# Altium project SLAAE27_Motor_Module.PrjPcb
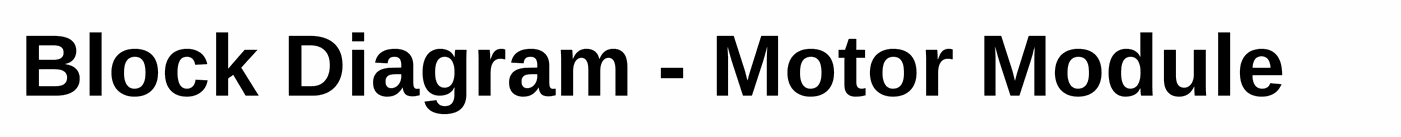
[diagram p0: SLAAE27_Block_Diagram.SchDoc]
Assembly Variant: 001; CopyrightYear: 2021; EVM_Orderable: N/A; PCB_Layout: Tessolve; PCB_Rev: E1; PRJ_Customer: Public Release; PRJ_Engineer: Sakshi Markhedkar; PRJ_Number: SLAAE27; PRJ_Title: SLAAE27_Motor_Module; SCH_Rev: E1; TechSupport: http://www.ti.com/support; TID: N/A
3 sheets, 169 parts. Net scope: global (net labels, ports and power ports of the same name join across sheets).
Board file: SLAAE27_Motor_Module_PCB.PcbDoc
Sheets:
  SLAAE27_Block_Diagram.SchDoc
  SLAAE27_MCU_&_Motor_Drivers.SchDoc
  SLAAE27_Motor_Module_Hardware.SchDoc

## Sheet SLAAE27_Block_Diagram.SchDoc: SLAAE27_Block_Diagram
size A2; Date: Not shown in title block; ApprovedBy: Not shown in title block; CheckedBy: Not shown in title block; Author: Not shown in title block; CompanyName: Not shown in title block; DrawnBy: Sakshi Markhedkar; Engineer: Not shown in title block; Organization: Not shown in title block; Address1: Not shown in title block; Address2: Not shown in title block; Address3: Not shown in title block; Address4: Not shown in title block; DocumentNumber: 1; Revision: Use project parameter SCH_Rev; SheetNumber: 1; SheetTotal: 3; PageSetup: Record=PageOptions¦CenterHorizontal=True¦CenterVertical=True¦PrintScale=1.00¦XCorrection=1.00¦YCorrection=1.00¦PrintKind=0¦BorderSize=5000000¦LeftOffset=0¦BottomOffset=0¦Orientation=2¦PaperLength=1000¦PaperWidth=1000¦Scale=100¦PaperSource=15¦PrintQuality=600¦MediaType=1¦DitherType=10¦PaperKind=Letter¦PrintScaleMode=1

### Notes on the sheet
- Block Diagram - Motor Module

## Sheet SLAAE27_MCU_&_Motor_Drivers.SchDoc: SLAAE27_MCU_&_Motor_Drivers
size A2; Date: Not shown in title block; ApprovedBy: Not shown in title block; CheckedBy: Not shown in title block; Author: Not shown in title block; CompanyName: Not shown in title block; DrawnBy: Sakshi Markhedkar; Engineer: Not shown in title block; Organization: Not shown in title block; Address1: Not shown in title block; Address2: Not shown in title block; Address3: Not shown in title block; Address4: Not shown in title block; DocumentNumber: 2; Revision: Use project parameter SCH_Rev; SheetNumber: 2; SheetTotal: 3; PageSetup: Record=PageOptions¦CenterHorizontal=True¦CenterVertical=True¦PrintScale=1.00¦XCorrection=1.00¦YCorrection=1.00¦PrintKind=0¦BorderSize=5000000¦LeftOffset=0¦BottomOffset=0¦Orientation=2¦PaperLength=1000¦PaperWidth=1000¦Scale=100¦PaperSource=15¦PrintQuality=600¦MediaType=1¦DitherType=10¦PaperKind=Letter¦PrintScaleMode=1
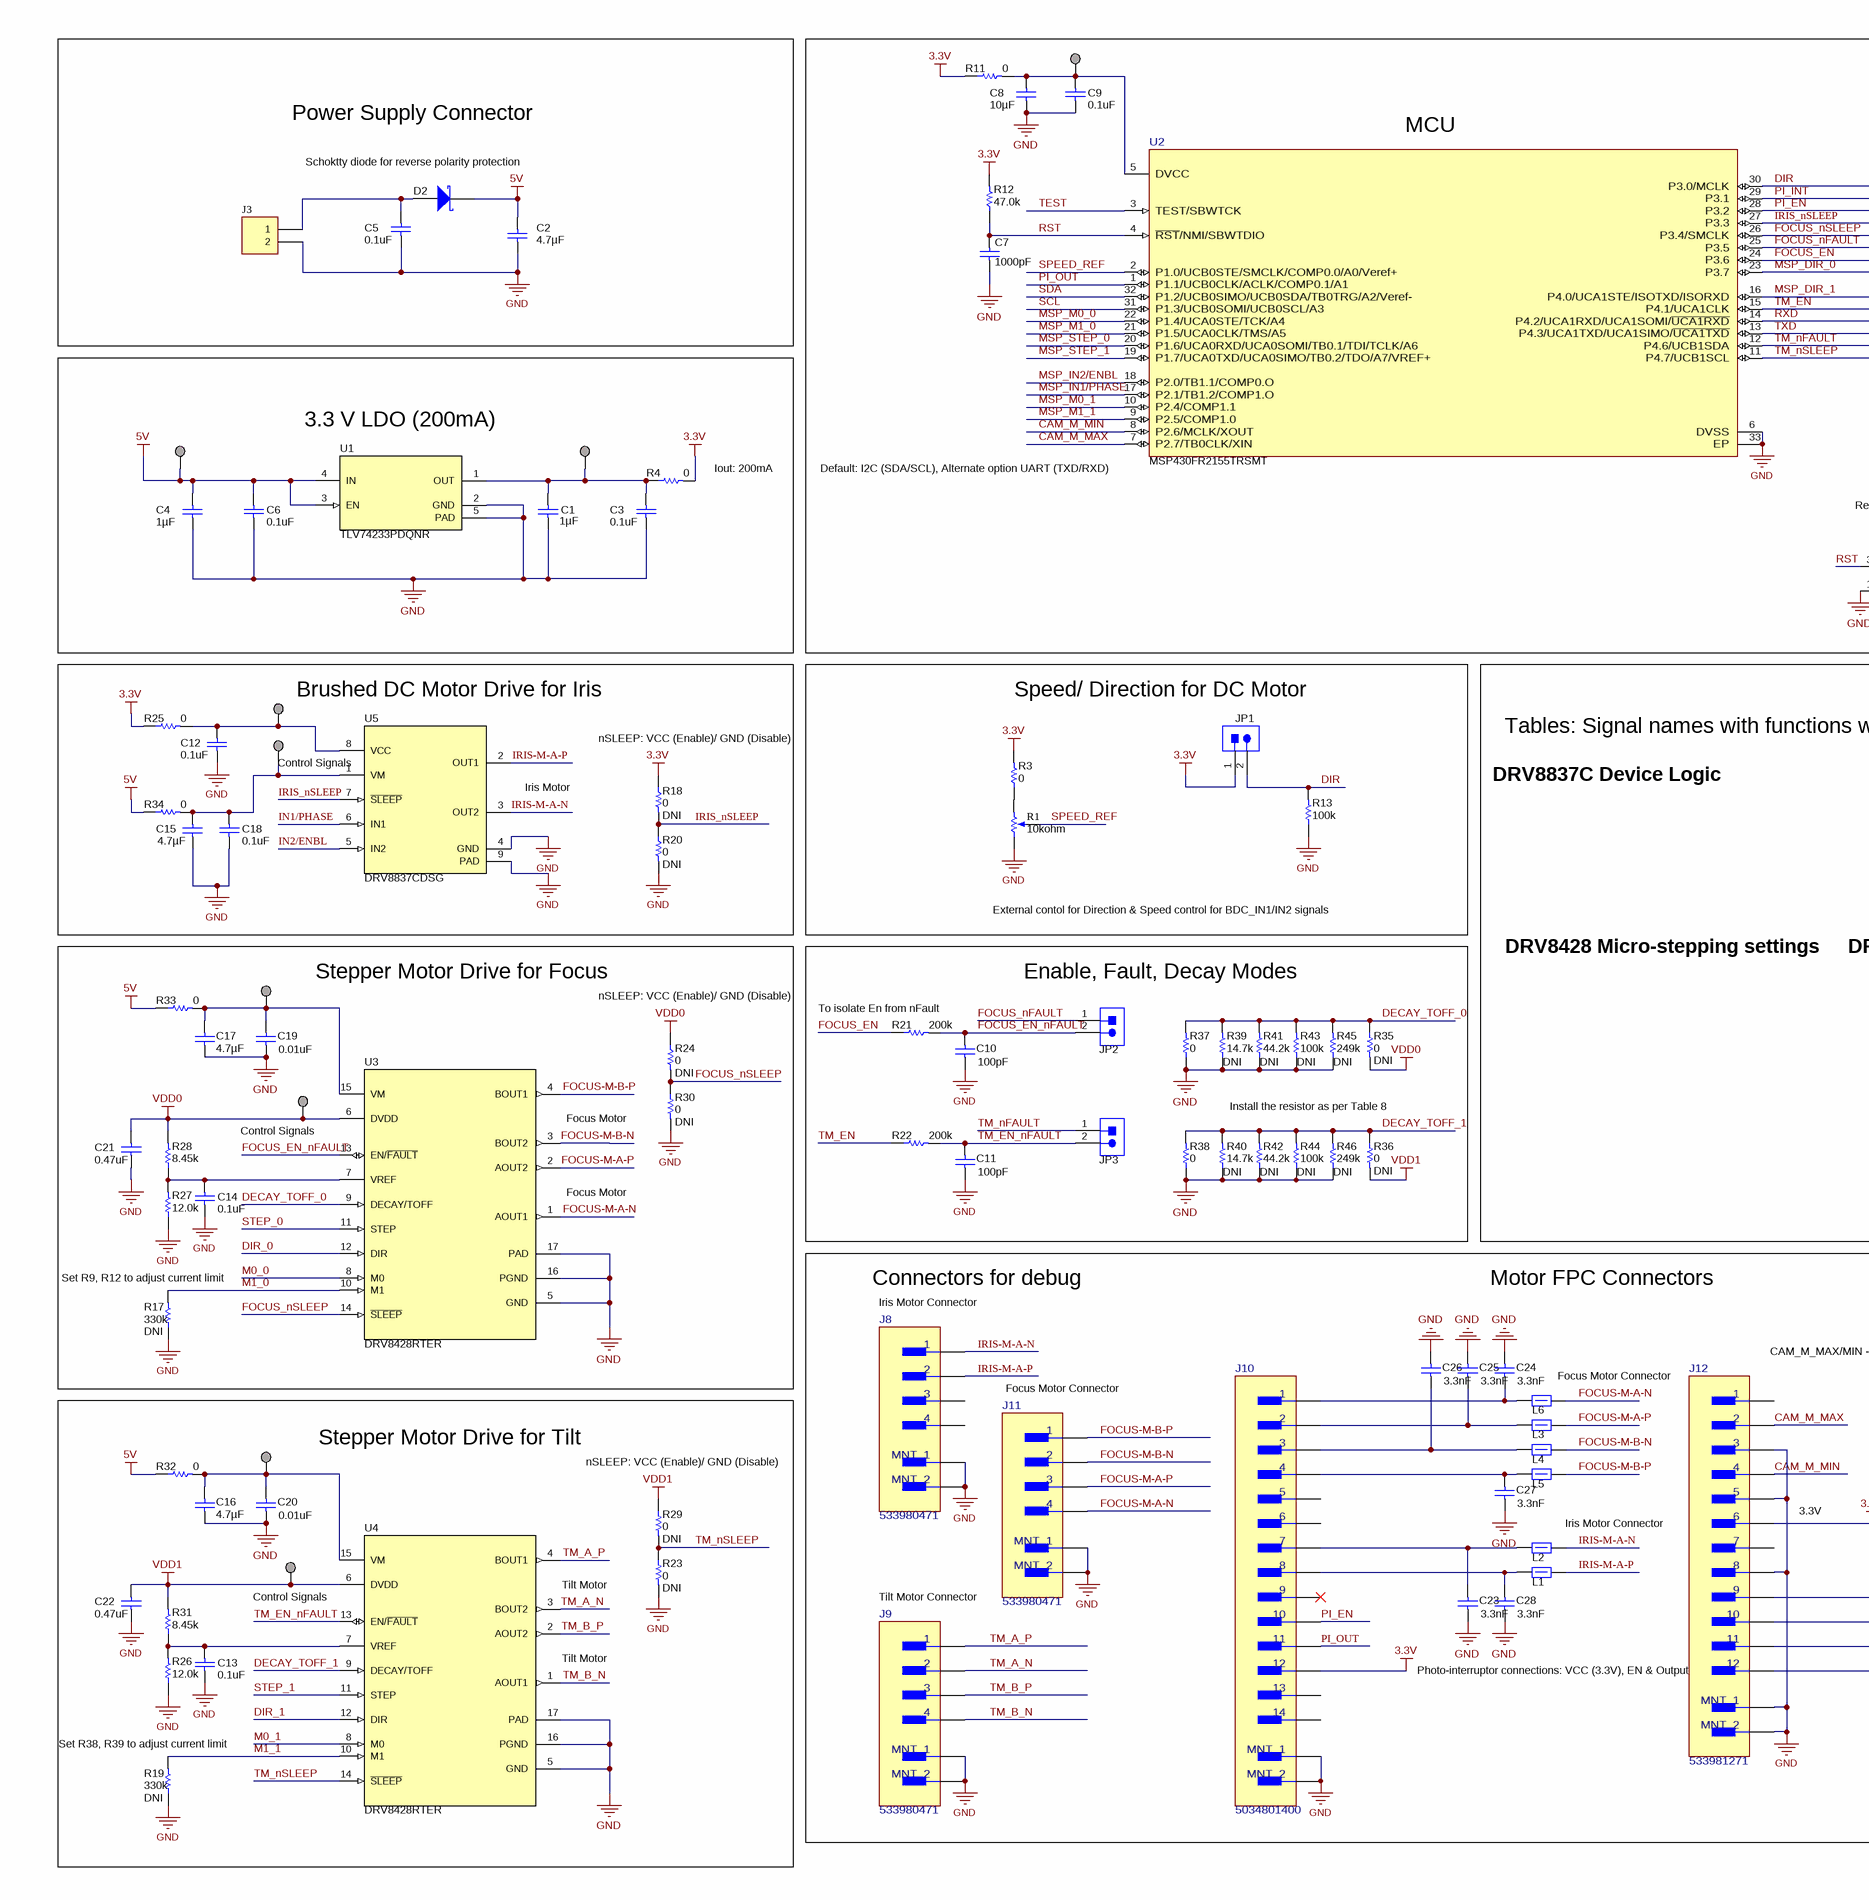
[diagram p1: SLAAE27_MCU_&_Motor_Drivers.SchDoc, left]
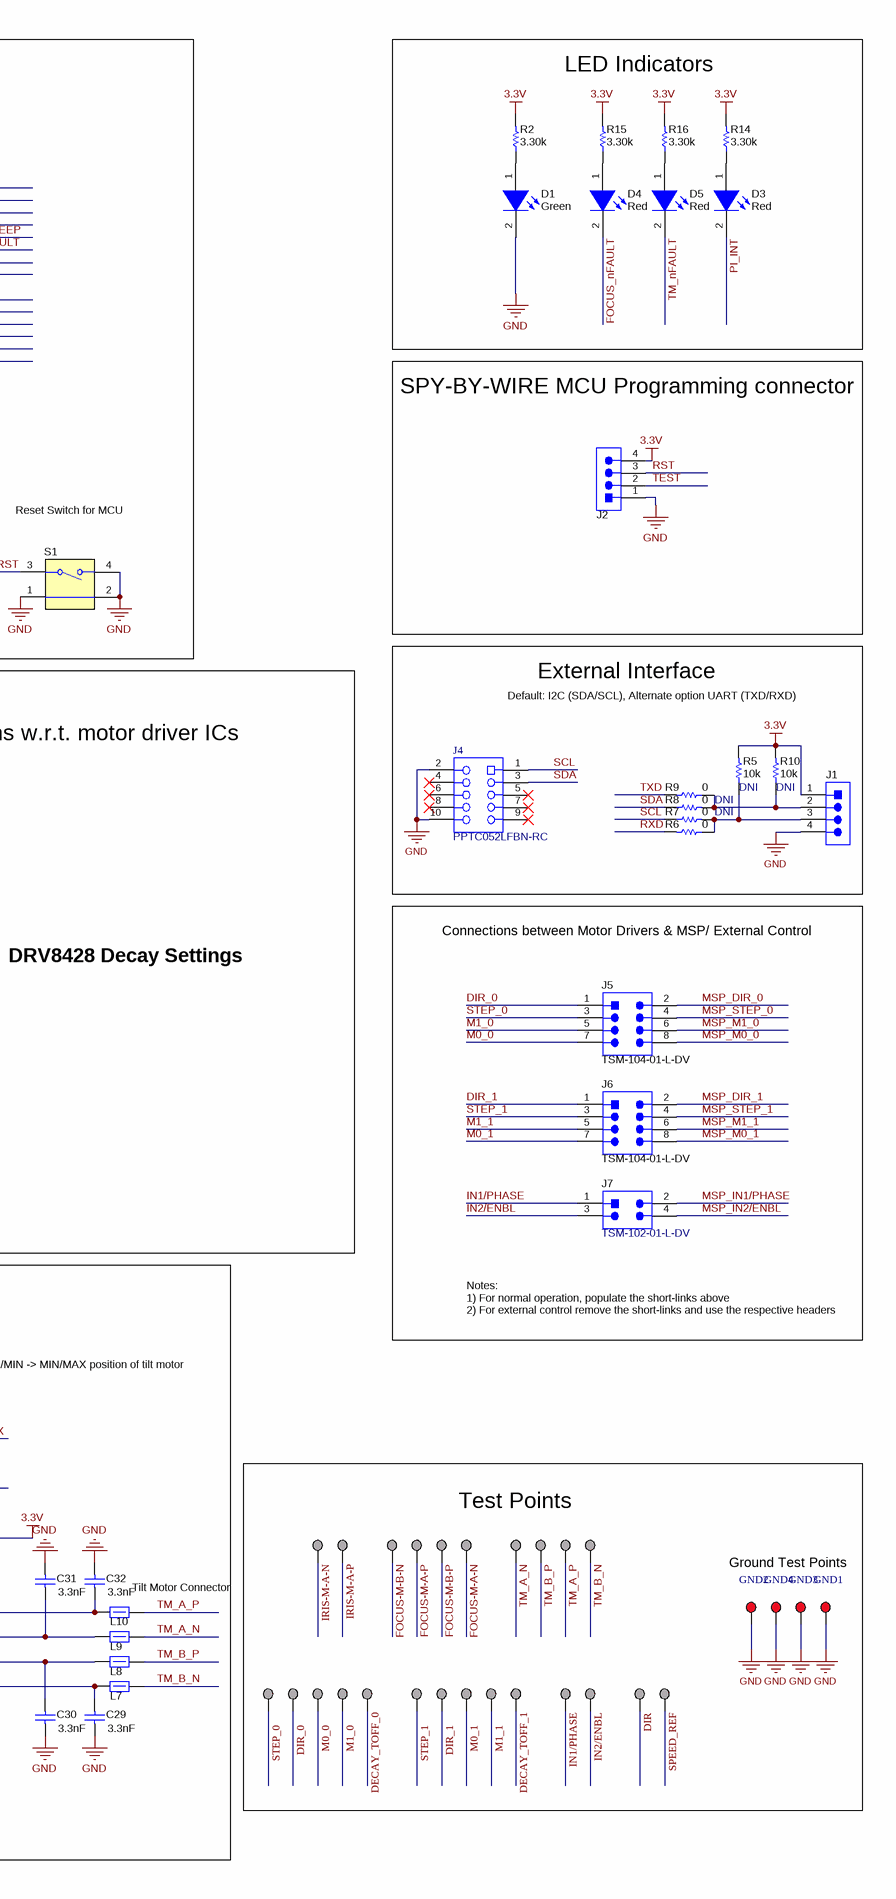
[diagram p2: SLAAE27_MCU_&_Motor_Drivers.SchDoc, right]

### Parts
3.3V  TP_SM_1MM  [TP_SM_1MM]  (value not drawn)  (no BOM)
3.3V_MCU  TP_SM_1MM  [TP_SM_1MM]  (value not drawn)  (no BOM)
5V  TP_SM_1MM  [TP_SM_1MM]  (value not drawn)  (no BOM)
C1  ValueDisplayed: 1µF  [0603]  (hidden comment: GRM188R71C105KA12D)
C2  Cap_F: 4.7µF  [0805_HV]  (hidden comment: C2012X7R1V475K125AC)
C3  value 0.1uF  [0402]
C4  ValueDisplayed: 1µF  [0603]  (hidden comment: GRM188R71C105KA12D)
C5  value 0.1uF  [0402]
C6  value 0.1uF  [0402]
C7  ValueDisplayed: 1000pF  [0402]  (hidden comment: 885012205044)
C8  Cap_F: 10µF  [0603]  (hidden comment: GRM188Z71A106MA73D)
C9  value 0.1uF  [0402]
C10  ValueDisplayed: 100pF  [0402]  (hidden comment: 0402YC101KAT2A)
C11  ValueDisplayed: 100pF  [0402]  (hidden comment: 0402YC101KAT2A)
C12  value 0.1uF  [0402]
C13  value 0.1uF  [0402]
C14  value 0.1uF  [0402]
C15  Cap_F: 4.7µF  [0805_HV]  (hidden comment: C2012X7R1V475K125AC)
C16  Cap_F: 4.7µF  [0603]  (hidden comment: GRM188Z71C475KE21D)
C17  Cap_F: 4.7µF  [0603]  (hidden comment: GRM188Z71C475KE21D)
C18  value 0.1uF  [0402]
C19  ValueDisplayed: 0.01uF  [0402]  (hidden comment: GRM155R71H103KA88D)
C20  ValueDisplayed: 0.01uF  [0402]  (hidden comment: GRM155R71H103KA88D)
C21  value 0.47uF  [0603]  (hidden comment: C1608X7R1H474K080AC)
C22  value 0.47uF  [0603]  (hidden comment: C1608X7R1H474K080AC)
C23  Cap_F: 3.3nF  [0402]  (hidden comment: CGA2B2X7R1H332K050BA)
C24  Cap_F: 3.3nF  [0402]  (hidden comment: CGA2B2X7R1H332K050BA)
C25  Cap_F: 3.3nF  [0402]  (hidden comment: CGA2B2X7R1H332K050BA)
C26  Cap_F: 3.3nF  [0402]  (hidden comment: CGA2B2X7R1H332K050BA)
C27  Cap_F: 3.3nF  [0402]  (hidden comment: CGA2B2X7R1H332K050BA)
C28  Cap_F: 3.3nF  [0402]  (hidden comment: CGA2B2X7R1H332K050BA)
C29  Cap_F: 3.3nF  [0402]  (hidden comment: CGA2B2X7R1H332K050BA)
C30  Cap_F: 3.3nF  [0402]  (hidden comment: CGA2B2X7R1H332K050BA)
C31  Cap_F: 3.3nF  [0402]  (hidden comment: CGA2B2X7R1H332K050BA)
C32  Cap_F: 3.3nF  [0402]  (hidden comment: CGA2B2X7R1H332K050BA)
D1  value Green  [APHHS1005_Green]  (hidden comment: APHHS1005CGCK)
D2  DB2W40200L  [SOD-123F]  (value not drawn)
D3  value Red  [APHHS1005_Red]  (hidden comment: APHHS1005SURCK)
D4  value Red  [APHHS1005_Red]  (hidden comment: APHHS1005SURCK)
D5  value Red  [APHHS1005_Red]  (hidden comment: APHHS1005SURCK)
DECAY_TOFF_0  TP_SM_1MM  [TP_SM_1MM]  (value not drawn)  (no BOM)
DECAY_TOFF_2  TP_SM_1MM  [TP_SM_1MM]  (value not drawn)  (no BOM)
DIR  TP_SM_1MM  [TP_SM_1MM]  (value not drawn)  (no BOM)
DIR_0  TP_SM_1MM  [TP_SM_1MM]  (value not drawn)  (no BOM)
DIR_1  TP_SM_1MM  [TP_SM_1MM]  (value not drawn)  (no BOM)
FOCUS-M-A-N  TP_SM_1MM  [TP_SM_1MM]  (value not drawn)  (no BOM)
FOCUS-M-A-P  TP_SM_1MM  [TP_SM_1MM]  (value not drawn)  (no BOM)
FOCUS-M-B-N  TP_SM_1MM  [TP_SM_1MM]  (value not drawn)  (no BOM)
FOCUS-M-B-P  TP_SM_1MM  [TP_SM_1MM]  (value not drawn)  (no BOM)
GND1  GND  [Keystone5005]  (value not drawn)
GND2  GND  [Keystone5005]  (value not drawn)
GND3  GND  [Keystone5005]  (value not drawn)
GND4  GND  [Keystone5005]  (value not drawn)
IN1/PHASE  TP_SM_1MM  [TP_SM_1MM]  (value not drawn)  (no BOM)
IN2/ENBL  TP_SM_1MM  [TP_SM_1MM]  (value not drawn)  (no BOM)
IRIS-M-A-N  TP_SM_1MM  [TP_SM_1MM]  (value not drawn)  (no BOM)
IRIS-M-A-P  TP_SM_1MM  [TP_SM_1MM]  (value not drawn)  (no BOM)
J1  GRPB041VWVN-RC  [Sullins_GRPB041VWVN-RC]  (value not drawn)
J2  GRPB041VWVN-RC  [Sullins_GRPB041VWVN-RC]  (value not drawn)
J3  Header 2  [HDR1X2]  (value not drawn)
J4  PPTC052LFBN-RC  [Sullins_xPxC052LFBN]
J5  TSM-104-01-L-DV  [Samtec_TSM-104-01-x-DV]
J6  TSM-104-01-L-DV  [Samtec_TSM-104-01-x-DV]
J7  TSM-102-01-L-DV  [Samtec_TSM-102-01-x-DV]
J8  533980471  [FP-533980471_HDR4-MFG]
J9  533980471  [FP-533980471_HDR4-MFG]
J10  5034801400  [FP-5034801400_SMD_8MM7_3MM6-MFG]
J11  533980471  [FP-533980471_HDR4-MFG]
J12  533981271  [FP-533981271_HDR12-MFG]
JP1  961102-6404-AR  [3M_961102-6404-AR]  (value not drawn)
JP2  961102-6404-AR  [3M_961102-6404-AR]  (value not drawn)
JP3  961102-6404-AR  [3M_961102-6404-AR]  (value not drawn)
L1  BLM18SG221TN1D  [0603]  (value not drawn)
L2  BLM18SG221TN1D  [0603]  (value not drawn)
L3  BLM18SG221TN1D  [0603]  (value not drawn)
L4  BLM18SG221TN1D  [0603]  (value not drawn)
L5  BLM18SG221TN1D  [0603]  (value not drawn)
L6  BLM18SG221TN1D  [0603]  (value not drawn)
L7  BLM18SG221TN1D  [0603]  (value not drawn)
L8  BLM18SG221TN1D  [0603]  (value not drawn)
L9  BLM18SG221TN1D  [0603]  (value not drawn)
L10  BLM18SG221TN1D  [0603]  (value not drawn)
M0_0  TP_SM_1MM  [TP_SM_1MM]  (value not drawn)  (no BOM)
M0_1  TP_SM_1MM  [TP_SM_1MM]  (value not drawn)  (no BOM)
M1_0  TP_SM_1MM  [TP_SM_1MM]  (value not drawn)  (no BOM)
M1_1  TP_SM_1MM  [TP_SM_1MM]  (value not drawn)  (no BOM)
R1  value 10kohm  [Bourns_3310Y]  (hidden comment: 3310Y-001-103L)
R2  ValueDisplayed: 3.30k  [0201]  (hidden comment: RC0201FR-073K3L)
R3  ValueDisplayed: 0  [0402]  (hidden comment: ERJ-2GE0R00X)
R4  ValueDisplayed: 0  [0402]  (hidden comment: ERJ-2GE0R00X)
R5  ValueDisplayed: 10k  Fiited: DNI  [0402]  (hidden comment: CRCW040210K0JNED)
R6  ValueDisplayed: 0  [0402]  (hidden comment: ERJ-2GE0R00X)
R7  ValueDisplayed: 0  Fitted: DNI  [0402]  (hidden comment: ERJ-2GE0R00X)
R8  ValueDisplayed: 0  Fitted: DNI  [0402]  (hidden comment: ERJ-2GE0R00X)
R9  ValueDisplayed: 0  [0402]  (hidden comment: ERJ-2GE0R00X)
R10  ValueDisplayed: 10k  Fitted: DNI  [0402]  (hidden comment: CRCW040210K0JNED)
R11  ValueDisplayed: 0  [0402]  (hidden comment: ERJ-2GE0R00X)
R12  ValueDisplayed: 47.0k  [0402]  (hidden comment: RC0402FR-0747KL)
R13  ValueDisplayed: 100k  [0402]  (hidden comment: RMCF0402FT100K)
R14  ValueDisplayed: 3.30k  [0201]  (hidden comment: RC0201FR-073K3L)
R15  ValueDisplayed: 3.30k  [0201]  (hidden comment: RC0201FR-073K3L)
R16  ValueDisplayed: 3.30k  [0201]  (hidden comment: RC0201FR-073K3L)
R17  ValueDisplayed: 330k  Fitted: DNI  [0402]  (hidden comment: RC0402FR-07330KL)
R18  ValueDisplayed: 0  Fitted: DNI  [0402]  (hidden comment: ERJ-2GE0R00X)
R19  ValueDisplayed: 330k  Fitted: DNI  [0402]  (hidden comment: RC0402FR-07330KL)
R20  ValueDisplayed: 0  Fitted: DNI  [0402]  (hidden comment: ERJ-2GE0R00X)
R21  ValueDisplayed: 200k  [0402]  (hidden comment: CRCW0402200KFKED)
R22  ValueDisplayed: 200k  [0402]  (hidden comment: CRCW0402200KFKED)
R23  ValueDisplayed: 0  Fitted: DNI  [0402]  (hidden comment: ERJ-2GE0R00X)
R24  ValueDisplayed: 0  Fitted: DNI  [0402]  (hidden comment: ERJ-2GE0R00X)
R25  ValueDisplayed: 0  [0402]  (hidden comment: ERJ-2GE0R00X)
R26  ValueDisplayed: 12.0k  [0402]  (hidden comment: CRCW040212K0FKED)
R27  ValueDisplayed: 12.0k  [0402]  (hidden comment: CRCW040212K0FKED)
R28  ValueDisplayed: 8.45k  [0402]  (hidden comment: CRCW04028K45FKED)
R29  ValueDisplayed: 0  Fitted: DNI  [0402]  (hidden comment: ERJ-2GE0R00X)
R30  ValueDisplayed: 0  Fitted: DNI  [0402]  (hidden comment: ERJ-2GE0R00X)
R31  ValueDisplayed: 8.45k  [0402]  (hidden comment: CRCW04028K45FKED)
R32  ValueDisplayed: 0  [0402]  (hidden comment: ERJ-2GE0R00X)
R33  ValueDisplayed: 0  [0402]  (hidden comment: ERJ-2GE0R00X)
R34  ValueDisplayed: 0  [0402]  (hidden comment: ERJ-2GE0R00X)
R35  ValueDisplayed: 0  Fitted: DNI  [0402]  (hidden comment: ERJ-2GE0R00X)
R36  ValueDisplayed: 0  Fitted: DNI  [0402]  (hidden comment: ERJ-2GE0R00X)
R37  ValueDisplayed: 0  [0402]  (hidden comment: ERJ-2GE0R00X)
R38  ValueDisplayed: 0  [0402]  (hidden comment: ERJ-2GE0R00X)
R39  ValueDisplayed: 14.7k  Fitted: DNI  [0402]  (hidden comment: CRCW040214K7FKED)
R40  ValueDisplayed: 14.7k  Fitted: DNI  [0402]  (hidden comment: CRCW040214K7FKED)
R41  ValueDisplayed: 44.2k  Fitted: DNI  [0402]  (hidden comment: CRCW040244K2FKED)
R42  ValueDisplayed: 44.2k  Fitted: DNI  [0402]  (hidden comment: CRCW040244K2FKED)
R43  ValueDisplayed: 100k  Fitted: DNI  [0402]  (hidden comment: RMCF0402FT100K)
R44  ValueDisplayed: 100k  Fitted: DNI  [0402]  (hidden comment: RMCF0402FT100K)
R45  ValueDisplayed: 249k  Fitted: DNI  [0402]  (hidden comment: CRCW0402249KFKED)
R46  ValueDisplayed: 249k  Fitted: DNI  [0402]  (hidden comment: CRCW0402249KFKED)
S1  1188E-1K2-V-TR  [SW_1188E]  (value not drawn)
SHNT1  Shunt Jumper  (value not drawn)
SPEED_REF  TP_SM_1MM  [TP_SM_1MM]  (value not drawn)  (no BOM)
STEP_0  TP_SM_1MM  [TP_SM_1MM]  (value not drawn)  (no BOM)
STEP_1  TP_SM_1MM  [TP_SM_1MM]  (value not drawn)  (no BOM)
TM_A_N  TP_SM_1MM  [TP_SM_1MM]  (value not drawn)  (no BOM)
TM_A_P  TP_SM_1MM  [TP_SM_1MM]  (value not drawn)  (no BOM)
TM_B_N  TP_SM_1MM  [TP_SM_1MM]  (value not drawn)  (no BOM)
TM_B_P  TP_SM_1MM  [TP_SM_1MM]  (value not drawn)  (no BOM)
U1  TLV74233PDQNR  [DQN0004A]
U2  MSP430FR2155TRSMT  [RSM0032B-MFG]
U3  DRV8428RTER  [RTE0016J]
U4  DRV8428RTER  [RTE0016J]
U5  DRV8837CDSG  [DSG0008A]
VCC  TP_SM_1MM  [TP_SM_1MM]  (value not drawn)  (no BOM)
VDD0  TP_SM_1MM  [TP_SM_1MM]  (value not drawn)  (no BOM)
VDD1  TP_SM_1MM  [TP_SM_1MM]  (value not drawn)  (no BOM)
VM_Focus  TP_SM_1MM  [TP_SM_1MM]  (value not drawn)  (no BOM)
VM_Iris  TP_SM_1MM  [TP_SM_1MM]  (value not drawn)  (no BOM)
VM_TM  TP_SM_1MM  [TP_SM_1MM]  (value not drawn)  (no BOM)

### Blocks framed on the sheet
Power Supply Connector: C2 C5 D2 J3
MCU: 3.3V_MCU C7-C9 R11 R12 S1 U2
LED Indicators: D1 D3-D5 R2 R14-R16
3.3 V LDO (200mA): 3.3V 5V C1 C3 C4 C6 R4 U1
SPY-BY-WIRE MCU Programming connector: J2
Brushed DC Motor Drive for Iris: C12 C15 C18 R18 R20 R25 R34 U5 VCC VM_Iris
Speed/ Direction for DC Motor: JP1 R1 R3 R13
External Interface: J1 J4 R5-R10
Connections between Motor Drivers & MSP/ External Control: J5-J7
Stepper Motor Drive for Focus: C14 C17 C19 C21 R17 R24 R27 R28 R30 R33 U3 VDD0 VM_Focus
Enable, Fault, Decay Modes: C10 C11 JP2 JP3 R21 R22 R35-R46
Stepper Motor Drive for Tilt: C13 C16 C20 C22 R19 R23 R26 R29 R31 R32 U4 VDD1 VM_TM
Test Points: DECAY_TOFF_0 DECAY_TOFF_2 DIR DIR_0 DIR_1 FOCUS-M-A-N FOCUS-M-A-P FOCUS-M-B-N FOCUS-M-B-P GND1-GND4 IN1/PHASE IN2/ENBL IRIS-M-A-N IRIS-M-A-P M0_0 M0_1 M1_0 M1_1 SPEED_REF STEP_0 STEP_1 TM_A_N TM_A_P TM_B_N TM_B_P

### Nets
3.3V: J1.1 J2.4 J10.12 J12.6 JP1.1 R2.2 R3.2 R4.2 R5.2 R10.2 R11.1 R12.2 R14.2 R15.2 R16.2 R18.1 R25.1
5V: 5V.1 C2.1 C4.1 C6.2 D2.1(K) R32.1 R33.1 R34.1 U1.3(EN) U1.4(IN)
GND: C1.2 C2.2 C3.1 C4.2 C5.1 C6.1 C7.2 C8.2 C9.1 C10.2 C11.2 C12.1 C13.1 C14.1 C15.2 C16.2 C17.2 C18.1 C19.2 C20.2 C21.2 C22.2 C23.2 C24.1 C25.1 C26.1 C27.2 C28.2 C29.2 C30.2 C31.1 C32.1 D1.2(K) GND1.1 GND2.1 GND3.1 GND4.1 J1.4 J2.1 J3.2 J4.2 J4.10 J8.5(MNT_1) J8.6(MNT_2) J9.5(MNT_1) J9.6(MNT_2) J10.15(MNT_1) J10.16(MNT_2) J11.5(MNT_1) J11.6(MNT_2) J12.3 J12.5 J12.8 J12.13(MNT_1) J12.14(MNT_2) R1.1(CCW) R13.1 R17.1 R19.1 R20.2 R23.2 R26.1 R27.1 R30.2 R37.1 R38.1 R39.1 R40.1 R41.1 R42.1 R43.1 R44.1 R45.1 R46.1 S1.1 S1.2 S1.4 U1.2(GND) U1.5(PAD) U2.6(DVSS) U2.33(EP) U3.5(GND) U3.16(PGND) U3.17(PAD) U4.5(GND) U4.16(PGND) U4.17(PAD) U5.4(GND) U5.9(PAD)
VDD0: C21.1 R24.1 R28.2 R35.2 U3.6(DVDD) VDD0.1
VDD1: C22.1 R29.1 R31.2 R36.2 U4.6(DVDD) VDD1.1
CAM_M_MAX: J12.2 U2.7(P2.7/TB0CLK/XIN)
CAM_M_MIN: J12.4 U2.8(P2.6/MCLK/XOUT)
DECAY_TOFF_0: DECAY_TOFF_0.1 R35.1 R37.2 R39.2 R41.2 R43.2 R45.2 U3.9(DECAY/TOFF)
DECAY_TOFF_1: DECAY_TOFF_2.1 R36.1 R38.2 R40.2 R42.2 R44.2 R46.2 U4.9(DECAY/TOFF)
DIR: DIR.1 JP1.2 R13.2 U2.30(P3.0/MCLK)
DIR_0: DIR_0.1 J5.1 U3.12(DIR)
DIR_1: DIR_1.1 J6.1 U4.12(DIR)
FOCUS-M-A-N: FOCUS-M-A-N.1 J11.4 L6.1 U3.1(AOUT1)
FOCUS-M-A-P: FOCUS-M-A-P.1 J11.3 L3.1 U3.2(AOUT2)
FOCUS-M-B-N: FOCUS-M-B-N.1 J11.2 L4.1 U3.3(BOUT2)
FOCUS-M-B-P: FOCUS-M-B-P.1 J11.1 L5.1 U3.4(BOUT1)
FOCUS_EN: R21.1 U2.24(P3.6)
FOCUS_EN_nFAULT: C10.1 JP2.2 R21.2 U3.13(EN/~{FAULT})
FOCUS_nFAULT: D4.2(K) JP2.1 U2.25(P3.5)
FOCUS_nSLEEP: R24.2 R30.1 U2.26(P3.4/SMCLK) U3.14(~{SLEEP})
IN1/PHASE: IN1/PHASE.1 J7.1 U5.6(IN1)
IN2/ENBL: IN2/ENBL.1 J7.3 U5.5(IN2)
IRIS-M-A-N: IRIS-M-A-N.1 J8.1 L2.1 U5.3(OUT2)
IRIS-M-A-P: IRIS-M-A-P.1 J8.2 L1.1 U5.2(OUT1)
IRIS_nSLEEP: R18.2 R20.1 U2.27(P3.3) U5.7(~{SLEEP})
M0_0: J5.7 M0_0.1 U3.8(M0)
M0_1: J6.7 M0_1.1 U4.8(M0)
M1_0: J5.5 M1_0.1 R17.2 U3.10(M1)
M1_1: J6.5 M1_1.1 R19.2 U4.10(M1)
MSP_DIR_0: J5.2 U2.23(P3.7)
MSP_DIR_1: J6.2 U2.16(P4.0/UCA1STE/ISOTXD/ISORXD)
MSP_IN1/PHASE: J7.2 U2.17(P2.1/TB1.2/COMP1.O)
MSP_IN2/ENBL: J7.4 U2.18(P2.0/TB1.1/COMP0.O)
MSP_M0_0: J5.8 U2.22(P1.4/UCA0STE/TCK/A4)
MSP_M0_1: J6.8 U2.10(P2.4/COMP1.1)
MSP_M1_0: J5.6 U2.21(P1.5/UCA0CLK/TMS/A5)
MSP_M1_1: J6.6 U2.9(P2.5/COMP1.0)
MSP_STEP_0: J5.4 U2.20(P1.6/UCA0RXD/UCA0SOMI/TB0.1/TDI/TCLK/A6)
MSP_STEP_1: J6.4 U2.19(P1.7/UCA0TXD/UCA0SIMO/TB0.2/TDO/A7/VREF+)
PI_EN: J10.10 U2.28(P3.2)
PI_INT: D3.2(K) U2.29(P3.1)
PI_OUT: J10.11 U2.1(P1.1/UCB0CLK/ACLK/COMP0.1/A1)
RST: C7.1 J2.3 R12.1 S1.3 U2.4(~{RST}/NMI/SBWTDIO)
RXD: R6.2 U2.14(P4.2/UCA1RXD/UCA1SOMI/~{UCA1RXD})
SCL: J4.1 R7.1 U2.31(P1.3/UCB0SOMI/UCB0SCL/A3)
SDA: J4.3 R8.1 U2.32(P1.2/UCB0SIMO/UCB0SDA/TB0TRG/A2/Veref-)
SPEED_REF: R1.2(WIPER) SPEED_REF.1 U2.2(P1.0/UCB0STE/SMCLK/COMP0.0/A0/Veref+)
STEP_0: J5.3 STEP_0.1 U3.11(STEP)
STEP_1: J6.3 STEP_1.1 U4.11(STEP)
TEST: J2.2 U2.3(TEST/SBWTCK)
TM_A_N: J9.2 L9.1 TM_A_N.1 U4.3(BOUT2)
TM_A_P: J9.1 L10.1 TM_A_P.1 U4.4(BOUT1)
TM_B_N: J9.4 L7.1 TM_B_N.1 U4.1(AOUT1)
TM_B_P: J9.3 L8.1 TM_B_P.1 U4.2(AOUT2)
TM_EN: R22.1 U2.15(P4.1/UCA1CLK)
TM_EN_nFAULT: C11.1 JP3.2 R22.2 U4.13(EN/~{FAULT})
TM_nFAULT: D5.2(K) JP3.1 U2.12(P4.6/UCB1SDA)
TM_nSLEEP: R23.1 R29.2 U2.11(P4.7/UCB1SCL) U4.14(~{SLEEP})
TXD: R9.2 U2.13(P4.3/UCA1TXD/UCA1SIMO/~{UCA1TXD})
Net3.3V_1: 3.3V.1 C1.1 C3.2 R4.1 U1.1(OUT)
Net3.3V_MCU_1: 3.3V_MCU.1 C8.1 C9.2 R11.2 U2.5(DVCC)
NetC5_2: C5.2 D2.2(A) J3.1
NetC12_2: C12.2 R25.2 U5.8(VCC) VCC.1
NetC13_2: C13.2 R26.2 R31.1 U4.7(VREF)
NetC14_2: C14.2 R27.2 R28.1 U3.7(VREF)
NetC15_1: C15.1 C18.2 R34.2 U5.1(VM) VM_Iris.1
NetC16_1: C16.1 C20.1 R32.2 U4.15(VM) VM_TM.1
NetC17_1: C17.1 C19.1 R33.2 U3.15(VM) VM_Focus.1
NetC23_1: C23.1 J10.7 L2.2
NetC24_2: C24.2 J10.1 L6.2
NetC25_2: C25.2 J10.2 L3.2
NetC26_2: C26.2 J10.3 L4.2
NetC27_1: C27.1 J10.4 L5.2
NetC28_1: C28.1 J10.8 L1.2
NetC29_1: C29.1 J12.12 L7.2
NetC30_1: C30.1 J12.11 L8.2
NetC31_2: C31.2 J12.10 L9.2
NetC32_2: C32.2 J12.9 L10.2
NetD1_1: D1.1(A) R2.1
NetD3_1: D3.1(A) R14.1
NetD4_1: D4.1(A) R15.1
NetD5_1: D5.1(A) R16.1
NetJ1_2: J1.2 R8.2 R9.1 R10.1
NetJ1_3: J1.3 R5.1 R6.1 R7.2
NetR1_3: R1.3(CW) R3.1

Not connected (* = marked no-connect by the designer): J4 4* 5* 6* 7* 8* 9*; J8 3 4; J10 5 6 9* 13 14; J12 1 7

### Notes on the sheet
- (near D2) Schoktty diode for reverse polarity protection
- (near R4) Iout: 200mA
- (near U2) Default: I2C (SDA/SCL), Alternate option UART (TXD/RXD)
- Reset Switch for MCU
- Default: I2C (SDA/SCL), Alternate option UART (TXD/RXD)
- Control Signals
- (near R18) nSLEEP: VCC (Enable)/ GND (Disable)
- Tables: Signal names with functions w.r.t. motor driver ICs
- (near U5) Iris Motor
- DRV8837C Device Logic
- External contol for Direction & Speed control for BDC_IN1/IN2 signals
- DRV8428 Micro-stepping settings
- DRV8428 Decay Settings
- (near R24) nSLEEP: VCC (Enable)/ GND (Disable)
- (near R21) To isolate En from nFault
- (near VDD0) Control Signals
- Focus Motor
- Install the resistor as per Table 8
- (near U3) Focus Motor
- (near R17) Set R9, R12 to adjust current limit
- (near J8) Iris Motor Connector
- Connectors for debug
- Motor FPC Connectors
- Notes:
  1) For normal operation, populate the short-links above
  2) For external control remove the short-links and use the respective headers
- Focus Motor Connector
- (near L6) Focus Motor Connector
- (near J12) CAM_M_MAX/MIN -> MIN/MAX position of tilt motor
- (near R29) nSLEEP: VCC (Enable)/ GND (Disable)
- 3.3V
- (near L2) Iris Motor Connector
- Tilt Motor Connector
- Ground Test Points
- (near VDD1) Control Signals
- (near U4) Tilt Motor
- (near J9) Tilt Motor Connector
- Photo-interruptor connections: VCC (3.3V), EN & Output
- (near R19) Set R38, R39 to adjust current limit

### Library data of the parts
3.3V 3.3V_MCU 5V DECAY_TOFF_0 DECAY_TOFF_2 DIR DIR_0 DIR_1 FOCUS-M-A-N FOCUS-M-A-P FOCUS-M-B-N FOCUS-M-B-P IN1/PHASE IN2/ENBL IRIS-M-A-N IRIS-M-A-P M0_0 M0_1 M1_0 M1_1 SPEED_REF STEP_0 STEP_1 TM_A_N TM_A_P TM_B_N TM_B_P VCC VDD0 VDD1 VM_Focus VM_Iris VM_TM = CMP-0003825-1: 1mm Test Point, SMT; Manufacturer: Any
C1 C4 = GRM188R71C105KA12D: CAP, CERM, 1 µF, 16 V,+/- 10%, X7R, 0603; Manufacturer: MuRata; Polarized: N; CompType: Capacitor; Value: 1uF; U/M: EA; Cap_F: 0.000001; Tolerance_%: 10; ESR_ohm: 0.011; Value1: 0.011 ohm; VDC_V: 16; Value2: 16V; TaMin_C: -55; TaMax_C: 125; SizeArea_mm2: 1.28; SizeAreaWB_mm2: 4.68; SizeX_mm: 1.6; SizeY_mm: 0.8; SizeZ_mm: 1; AEC Category: Q200; Green_Lifecycle: Active; Green_REACh: Passed
C2 C15 = CMP-0007885-2: CAP, CERM, 4.7 uF, 35 V, +/- 10%, X7R, 0805; Manufacturer: TDK; TaMin_C: -55°C; ESR_ohm: 2.346m; Polarized: N; SizeAreaWB_mm2: 6.75; Value1: 0.002346 ohm; U/M: EA; Value: 4.7uF; TaMax_C: 125°C; SizeZ_mm: 1.45; SizeX_mm: 2; SizeY_mm: 1.25; Cap_Case: 0805; Value2: 35V; SizeArea_mm2: 2.5; IRMS_A: 4.26021A; AEC Category: Q200
C3 C5 C6 C9 C12-C14 C18 = Cap: CAP CER 0.1UF 16V 10% X7R 0402; Manufacturer: Murata Electronics North America; MFG Part Number: GRM155R71C104KA88D
C7 = 885012205044: CAP, CERM, 1000 pF, 25 V, +/- 10%, X7R, 0402; Manufacturer: Wurth Elektronik; Polarized: N; CompType: Capacitor; Value: 1000pF; U/M: EA; Cap_F: 0.000000001; Tolerance_%: 10; Value1: Unknown; VDC_V: 25; Value2: 25V; TaMin_C: -55; TaMax_C: 125; SizeArea_mm2: 0.5; SizeAreaWB_mm2: 3; SizeX_mm: 1; SizeZ_mm: 0.6; AEC Category: Q200
C8 = CMP-0007497-4: CAP, CERM, 10 uF, 10 V, +/- 20%, X7R, 0603; Manufacturer: MuRata; TaMin_C: -55°C; Polarized: N; SizeAreaWB_mm2: 4.68; Value1: Unknown; U/M: EA; Value: 10uF; TaMax_C: 125°C; SizeZ_mm: 1; SizeX_mm: 1.6; SizeY_mm: 0.8; Value2: 10V; SizeArea_mm2: 1.28; AEC Category: Q200
C10 C11 = CMP-0006200-2: CAP, CERM, 100 pF, 16 V, +/- 10%, X7R, 0402; Manufacturer: AVX; TaMin_C: -55°C; Polarized: N; SizeAreaWB_mm2: 3; Value1: Unknown; U/M: EA; Value: 100pF; TaMax_C: 125°C; SizeZ_mm: 0.6; SizeX_mm: 1; SizeY_mm: 0.5; Value2: 16V; AEC Category: Q200
C16 C17 = CMP-0064936-4: CAP, CERM, 4.7 uF, 16 V,+/- 10%, X7R, 0603; Manufacturer: MuRata; TaMin_C: -55°C; Polarized: N; SizeAreaWB_mm2: 4.68; Value1: Unknown; U/M: EA; Value: 4.7uF; TaMax_C: 125°C; SizeZ_mm: 1; SizeX_mm: 1.6; SizeY_mm: 0.8; Value2: 16V; SizeArea_mm2: 1.28; AEC Category: Q200
C19 C20 = CMP-0006674-1: CAP, CERM, 0.01 uF, 50 V, +/- 10%, X7R, 0402; Manufacturer: MuRata; TaMin_C: -55°C; Polarized: N; SizeAreaWB_mm2: 3; Value1: Unknown; U/M: EA; Value: 0.01uF; TaMax_C: 125°C; SizeZ_mm: 0.6; SizeX_mm: 1; SizeY_mm: 0.5; Value2: 50V; Cap_F: 10nF; AEC Category: Q200
C21 C22 = CMP-0007050-3: CAP, CERM, 0.47 uF, 50 V, +/- 10%, X7R, 0603; Manufacturer: TDK; TaMin_C: -55°C; ESR_ohm: 0.010974; Polarized: N; SizeAreaWB_mm2: 4.68; Value1: 0.010974 ohm; U/M: EA; TaMax_C: 125°C; SizeZ_mm: 1; SizeX_mm: 1.6; SizeY_mm: 0.8; Value2: 50V; SizeArea_mm2: 1.28; Cap_F: 470nF; IRMS_A: 1.57483A; AEC Category: Q200
C23-C32 = CMP-0006319-1: CAP, CERM, 3300 pF, 50 V, +/- 10%, X7R, AEC-Q200 Grade 1, 0402; Manufacturer: TDK; TaMin_C: -55°C; ESR_ohm: 0.785178; Polarized: N; SizeAreaWB_mm2: 3; Value1: 0.785178 ohm; U/M: EA; Value: 3300pF; TaMax_C: 125°C; SizeZ_mm: 0.6; SizeX_mm: 1; SizeY_mm: 0.5; Value2: 50V; AEC Qualified: Y; IRMS_A: 272.902mA; AEC Category: Q200
D1 = APHHS1005CGCK: LED, Green, SMD; Manufacturer: Kingbright; Vf_V: 2.1; Value2: 2.1V; Io_A: 0.02; Vr_V: 5; Ir_A: 1e-005; Tjmax_C: 85; Power_TotalModule: 0.075; Value1: 0.075W; Angle: 120; SizeAreaWB_mm2: 3; SizeArea_mm2: 0.5; SizeX_mm: 1; SizeZ_mm: 0.6; U/M: EA
D2 = CMP-0028849-2: Diode, Schottky, 40 V, 2 A, SOD-123F; Manufacturer: Panasonic; SizeX_mm: 3.5; TJmax_C: 150°C; Green_REACh: Incomplete; SizeY_mm: 1.6; Green_Lifecycle: Not Set; Value1: 2A; Vf_V: 470mV; Value2: 0.47V; AEC Category: Q101; SizeZ_mm: 1.1; SizeArea_mm2: 5.6; Vr_V: 40V; Value: 40V; AEC Qualified: N; SizeAreaWB_mm2: 11.7
D3-D5 = APHHS1005SURCK: LED, Red, SMD; Manufacturer: Kingbright; Vf_V: 1.95; Value2: 1.95V; Io_A: 0.02; Vr_V: 5; Ir_A: 1e-005; Tjmax_C: 85; Power_TotalModule: 0.075; Value1: 0.075W; Angle: 120; SizeAreaWB_mm2: 3; SizeArea_mm2: 0.5; SizeX_mm: 1; SizeZ_mm: 0.6; U/M: EA
GND1-GND4 = CMP-0055142-1: Test Point, Compact, Red, TH; Manufacturer: Keystone; CNHeader: FALSE; Green_Lifecycle: Active; Green_REACh: Passed; ContactFinish: Silver; CT: TRUE
J1 J2 = GRPB041VWVN-RC: Header, 50mil, 4x1, Gold, TH; Manufacturer: Sullins Connector Solutions; SymbolCreator: a0412235
J3 = Header 2: CONN HEADER VERT SGL 2POS GOLD; Manufacturer: 3M; MFG Part Number: 961102-6404-AR; Value: 2-Pin Header
J4 = CMP-0054661-1: Receptacle, 2.54mm, 5x2, Gold, TH; Manufacturer: Sullins Connector Solutions; CNHeader: FALSE; Current_A: 3A; Gender: Female; Voltage_V: 250V; CompType: Socket Strip; Row_Count: 2; RowSpacing_mm: 2.54; ContactFinish: Tin; CT: TRUE; Cert_UL: Y
J5 J6 = CMP-0075593-1: Header, 2.54mm, 4x2, Gold, SMT; Manufacturer: Samtec; Pitch_mm: 2.54; Gender: Male; Cert_CSA: Y; Green_REACh: Passed; Current_A: 4.9A; Voltage_V: 475V; CT: False; Shrouded: N; Green_Lifecycle: Active; Row_Count: 2; CNHeader: True
J7 = CMP-0055559-1: Header, 2.54mm, 2x2, Gold, SMT; Manufacturer: Samtec; CNHeader: TRUE; Shrouded: N; Gender: Male; Cert_CSA: Y; Voltage_V: 475V; Row_Count: 2; Pitch_mm: 2.54; CT: FALSE
J8 J9 J11 = CMP-0088984-1: Manufacturer: Molex; SizeZ_mm: 5.1mm; Conn Gender: Male; AEC Qualified: No; Conn Orientation: Vertical; Current_A: 1A; TaMin_C: -40°C; ContactFinish: Tin, Nickel; TaMax_C: +105°C; DUT-Pitch_mm: 1.25mm; Voltage_V: 125V; Standoff Height: 0.05mm; Row_Count: 1
J10 = CMP-0088983-1: Manufacturer: Molex; Voltage_V: 50V; Current_A: 500mA; Conn Orientation: Right Angle; AEC Qualified: No; ContactFinish: Gold,Nickel; SizeZ_mm: 2.12mm; Conn Gender: Male; DUT-Pitch_mm: 0.5mm
J12 = CMP-0088985-1: Manufacturer: Molex; Conn Gender: Male; DUT-Pitch_mm: 1.25mm; ContactFinish: Tin, Nickel; SizeZ_mm: 5.1mm; Current_A: 1A; AEC Qualified: No; Voltage_V: 125V; Conn Orientation: Vertical; Row_Count: 1; Standoff Height: 0.05mm
JP1-JP3 = CMP-0075197-1: Header, 2.54mm, 2x1, TH; Manufacturer: 3M; CNHeader: True; Current_A: 2A; Green_Lifecycle: Active; Shrouded: N; Gender: Male; Green_REACh: Passed; Voltage_V: 1kV; Row_Count: 1; Pitch_mm: 2.54; ContactFinish: Gold; CT: False; Cert_UL: Y
L1-L10 = CMP-0003353-1: Ferrite Bead, 220 ohm @ 100 MHz, 2.5 A, 0603; Manufacturer: MuRata; ZTyp@100MHz_Ohm: 220; SizeAreaWB_mm2: 4.68; DCR_ohm: 0.04; Value1: 0.04 ohm; Value: 220 ohm; Imax_A: 2.5A; SizeZ_mm: 1; SizeX_mm: 1.6; SizeY_mm: 0.8; SizeArea_mm2: 1.28
R1 = CMP-0001773-2: Potentiometer, 10k ohm, 0.25W, TH; Manufacturer: Bourns; CompType: Trimmer
R2 R14-R16 = RC0201FR-073K3L: RES, 3.30 k, 1%, 0.05 W, 0201; Manufacturer: Yageo America; CompType: Resistor; Value: 3.30k; Res_ohm: 3300; Value_Code: 3k30; Tolerance_%: 1; Power_W: 0.05; Value2: 0.05W; VDC_V: 25; TempCo: 200 ppm/C; SizeArea_mm2: 0.18; SizeX_mm: 0.6; SizeY_mm: 0.3; SizeZ_mm: 0.26; U/M: EA; AEC Category: Q200; AEC Qualified: N
R3 R4 R6-R9 R11 R18 R20 R23-R25 R29 R30 R32-R38 = CMP-0026992-3: RES, 0, 5%, 0.1 W, AEC-Q200 Grade 0, 0402; Manufacturer: Panasonic; Power_W: 100mW; TempCo: 600 ppm/C; Value_Code: 0000; Value: 0; EIA_Code: E24; SizeX_mm: 1; SizeY_mm: 0.5; SizeZ_mm: 0.6; Value2: 0.1W; AEC Qualified: Y; VDC_V: 50V; AEC Category: Q200; SizeAreaWB_mm2: 3
R5 R10 = CMP-0026825-1: RES, 10 k, 5%, 0.063 W, 0402; Manufacturer: Vishay-Dale; Power_W: 63mW; TempCo: 200 ppm/C; Value_Code: 10k0; U/M: EA; Value: 10k; EIA_Code: E24; SizeX_mm: 1; SizeY_mm: 0.5; SizeZ_mm: 0.6; Value2: 0.063W; VDC_V: 50V; AEC Category: Q200
R12 = RC0402FR-0747KL: RES, 47.0 k, 1%, 0.0625 W, 0402; Manufacturer: Yageo America; CompType: Resistor; Value: 47.0k; Res_ohm: 47000; Value_Code: 47k0; Tolerance_%: 1; Power_W: 0.0625; VDC_V: 50; TempCo: 100 ppm/C; SizeArea_mm2: 0.5; SizeZ_mm: 0.6; U/M: EA; AEC Category: Q200; AEC Qualified: N
R13 = CMP-0026753-1: RES, 100 k, 1%, 0.063 W, AEC-Q200 Grade 0, 0402; Manufacturer: Stackpole Electronics Inc; Power_W: 63mW; TempCo: 100 ppm/C; U/M: EA; Value: 100k; EIA_Code: E96; SizeX_mm: 1; SizeY_mm: 0.5; SizeZ_mm: 0.6; Value2: 0.063W; AEC Qualified: Y; VDC_V: 50V; AEC Grade: 0; AEC Category: Q200; Fitted: DNI
R17 R19 = CMP-0026731-1: RES, 330 k, 1%, 0.0625 W, 0402; Manufacturer: Yageo America; Power_W: 62.5mW; TempCo: 100 ppm/C; U/M: EA; Value: 330k; SizeX_mm: 1; SizeY_mm: 0.5; SizeZ_mm: 0.6; AEC Qualified: N; VDC_V: 50V; AEC Category: Q200
R21 R22 = CMP-0026158-2: RES, 200 k, 1%, 0.063 W, AEC-Q200 Grade 0, 0402; Manufacturer: Vishay-Dale; Power_W: 63mW; TempCo: 100 ppm/C; Value: 200k; EIA_Code: E96; SizeX_mm: 1; SizeY_mm: 0.5; SizeZ_mm: 0.6; Value2: 0.063W; AEC Qualified: Y; VDC_V: 50V; AEC Category: Q200; AEC Grade: 0
R26 R27 = CMP-0025990-3: RES, 12.0 k, 1%, 0.063 W, AEC-Q200 Grade 0, 0402; Manufacturer: Vishay-Dale; Power_W: 63mW; TempCo: 100 ppm/C; Value_Code: 12k0; Value: 12.0k; Res_ohm: 12k; SizeX_mm: 1; SizeY_mm: 0.5; SizeZ_mm: 0.6; Value2: 0.063W; AEC Qualified: Y; VDC_V: 50V; AEC Grade: 0; AEC Category: Q200
R28 R31 = CMP-0026590-2: RES, 8.45 k, 1%, 0.063 W, AEC-Q200 Grade 0, 0402; Manufacturer: Vishay-Dale; Power_W: 63mW; TempCo: 100 ppm/C; Value_Code: 8k45; Value: 8.45k; EIA_Code: E96; SizeX_mm: 1; SizeY_mm: 0.5; SizeZ_mm: 0.6; Value2: 0.063W; AEC Qualified: Y; VDC_V: 50V; AEC Category: Q200; AEC Grade: 0
R39 R40 = CMP-0026017-1: RES, 14.7 k, 1%, 0.063 W, 0402; Manufacturer: Vishay-Dale; Power_W: 63mW; TempCo: 100 ppm/C; Value_Code: 14k7; U/M: EA; Value: 14.7k; EIA_Code: E96; SizeX_mm: 1; SizeY_mm: 0.5; SizeZ_mm: 0.6; Value2: 0.063W; VDC_V: 50V; AEC Category: Q200
R41 R42 = CMP-0026383-2: RES, 44.2 k, 1%, 0.063 W, AEC-Q200 Grade 0, 0402; Manufacturer: Vishay-Dale; Power_W: 63mW; TempCo: 100 ppm/C; Value_Code: 44k2; Value: 44.2k; EIA_Code: E96; SizeX_mm: 1; SizeY_mm: 0.5; SizeZ_mm: 0.6; Value2: 0.063W; AEC Qualified: Y; VDC_V: 50V; AEC Category: Q200; AEC Grade: 0
R43 R44 = CMP-0026753-1: RES, 100 k, 1%, 0.063 W, AEC-Q200 Grade 0, 0402; Manufacturer: Stackpole Electronics Inc; Power_W: 63mW; TempCo: 100 ppm/C; U/M: EA; Value: 100k; EIA_Code: E96; SizeX_mm: 1; SizeY_mm: 0.5; SizeZ_mm: 0.6; Value2: 0.063W; AEC Qualified: Y; VDC_V: 50V; AEC Grade: 0; AEC Category: Q200
R45 R46 = CMP-0026193-2: RES, 249 k, 1%, 0.063 W, AEC-Q200 Grade 0, 0402; Manufacturer: Vishay-Dale; Power_W: 63mW; TempCo: 100 ppm/C; Value: 249k; EIA_Code: E96; SizeX_mm: 1; SizeY_mm: 0.5; SizeZ_mm: 0.6; Value2: 0.063W; AEC Qualified: Y; VDC_V: 50V; AEC Category: Q200; AEC Grade: 0
S1 = CMP-0002328-1: Switch, SPST, 0.05 A, 12 VDC, SMD; Manufacturer: Diptronics; CurrentRating_mA: 50A; PositionCount: 1; SizeX_mm: 7.8; SizeY_mm: 3.5; SizeArea_mm2: 27.3; VDC_V: 12V; SizeAreaWB_mm2: 53.9
SHNT1 = Shunt Jumper: SHUNT JUMPER .1" BLACK GOLD; Manufacturer: 3M; MFG Part Number: 969102-0000-DA
U1 = CMP-0079101-2: 200-mA, Small Size, Low-Dropout Linear Voltage Regulator, DQN0004A (X2SON-4); Alternate Manufacturer: Texas Instruments; SizeAreaWB_mm2: 4; SizeZ_mm: 0.4; SizeX_mm: 1; CompType: IC; AEC Qualified: N; AEC Category: Q200
U2 = CMP-0089265-1: CPU16 MSP430™ FRAM Microcontroller IC 16-Bit 24MHz 32KB (32K x 8) FRAM 32-VQFN (4x4); Manufacturer: Texas Instruments; TaMax_C: +105°C; Number Of I/Os: 28; Standoff Height: 0mm; Number Of I2C Channels: 2; Memory Size: 32KBytes; Min Supply Voltage: 1.8V; Ram Size: 4KBytes; Number Of Cores: 1; Number Of Spi Channels: 4; Memory Type: RAM; AEC Qualified: No; TJmax_C: +115°C; SizeZ_mm: 1mm; Core Architecture: RISC; Nominal Supply Current: 185-280uA; Data Bus Width: 8bits; Interface: I2C,SPI,UART,SCI,IrDA,Other; TaMin_C: -40°C; Max Supply Voltage: 3.6V; Number Of Adc Channels: 8
U3 U4 = CMP-0861028-1: Stepper Drivers With Integrated Current Sense, 1/256 Microstepping, STEP/DIR Interface and smart tune Technology, RTE0016J (WQFN-16); Manufacturer: Texas Instruments; CompType: IC; SizeZ_mm: 0.8; AEC Category: Q200; SizeX_mm: 3; SizeAreaWB_mm2: 16; AEC Qualified: N; SizeArea_mm2: 9
U5 = CMP-0013449-3: 1-A Low-Voltage H-Bridge Driver, DSG0008A (WSON-8); Manufacturer: Texas Instruments; SizeZ_mm: 0.8; SizeX_mm: 2; SizeArea_mm2: 4; CompType: IC; U/M: EA; SizeAreaWB_mm2: 9

## Sheet SLAAE27_Motor_Module_Hardware.SchDoc: SLAAE27_Hardware
size A2; Date: Not shown in title block; ApprovedBy: Not shown in title block; CheckedBy: Not shown in title block; Author: Not shown in title block; CompanyName: Not shown in title block; DrawnBy: Sakshi Markhedkar; Engineer: Not shown in title block; Organization: Not shown in title block; Address1: Not shown in title block; Address2: Not shown in title block; Address3: Not shown in title block; Address4: Not shown in title block; DocumentNumber: 3; Revision: Use project parameter SCH_Rev; SheetNumber: 3; SheetTotal: 3; PageSetup: Record=PageOptions¦CenterHorizontal=True¦CenterVertical=True¦PrintScale=1.00¦XCorrection=1.00¦YCorrection=1.00¦PrintKind=0¦BorderSize=5000000¦LeftOffset=0¦BottomOffset=0¦Orientation=2¦PaperLength=1000¦PaperWidth=1000¦Scale=100¦PaperSource=15¦PrintQuality=600¦MediaType=1¦DitherType=10¦PaperKind=Letter¦PrintScaleMode=1
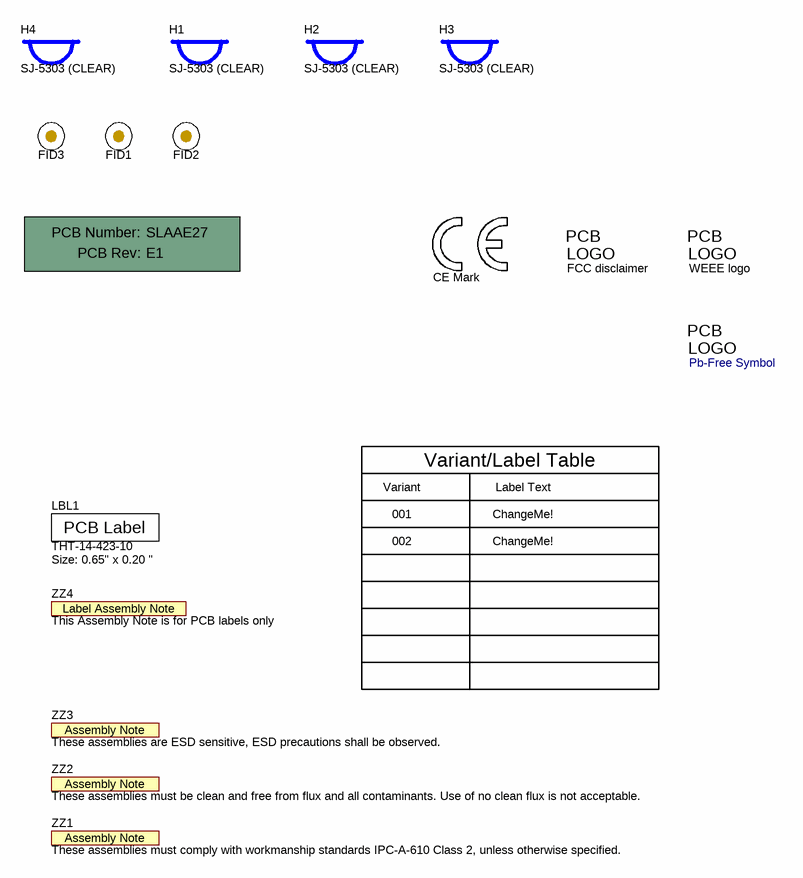
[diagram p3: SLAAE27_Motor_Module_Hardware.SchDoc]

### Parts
!PCB1  Printed Circuit Board  (value not drawn)  (mechanical)
FID1  Fiducial  [Fiducial10-20]  (value not drawn)
FID2  Fiducial  [Fiducial10-20]  (value not drawn)
FID3  Fiducial  [Fiducial10-20]  (value not drawn)
H1  SJ-5303 (CLEAR)  [Bumpon_SJ5003Transparent]
H2  SJ-5303 (CLEAR)  [Bumpon_SJ5003Transparent]
H3  SJ-5303 (CLEAR)  [Bumpon_SJ5003Transparent]
H4  SJ-5303 (CLEAR)  [Bumpon_SJ5003Transparent]
LBL1  THT-14-423-10  Note: Size: 0.65" x 0.20 "  [Label_650x200]
Logo2  WEEE logo  [WEEE_Minimum]  (no BOM)
Logo3  Pb-Free Symbol  [Pb-Free_Overlay_Small]  (no BOM)
Logo4  CE Mark  [CE_Mark_5mm]  (no BOM)
Logo5  FCC disclaimer  [FCC_disclaimer]  (graphical)
ZZ1  These assemblies must comply with workmanship standards IPC-A-610 Class 2, unless otherwise specified.  [AssemblyNote]  (no BOM)
ZZ2  These assemblies must be clean and free from flux and all contaminants. Use of no clean flux is not acceptable.  [AssemblyNote]  (no BOM)
ZZ3  These assemblies are ESD sensitive, ESD precautions shall be observed.  [AssemblyNote]  (no BOM)
ZZ4  This Assembly Note is for PCB labels only  [AssemblyNoteLabel]  (no BOM)

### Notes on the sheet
- Variant
- Variant/Label Table
- Label Text
- 001
- 002
- ChangeMe!

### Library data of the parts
!PCB1 = CMP-0003618-2: Manufacturer: Any; PartNumber: SLAAE27
FID1-FID3 = CMP-0077181-1: Fiducial mark.  There is nothing to buy or mount.
H1-H4 = CMP-0003620-1: Bumpon, Hemisphere, 0.44 X 0.20, Clear; Manufacturer: 3M
LBL1 = CMP-0003625-1: Thermal Transfer Printable Labels, 0.650" W x 0.200" H - 10,000 per roll; Manufacturer: Brady; CompType: Label
Logo2 = CMP-0074769-1
Logo3 = CMP-0074839-1: SymbolCreator: a0412235
Logo4 = CMP-0074844-1: SymbolCreator: a0412235
Logo5 = CMP-0074847-1: FCC_disclaimer; Library Reference: Logo
ZZ1 = CMP-0077238-1
ZZ2 = CMP-0077237-1
ZZ3 = CMP-0077236-1
ZZ4 = CMP-0003616-3

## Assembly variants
001: not fitted FID1 FID2 FID3 R5 R7 R8 R10 R17 R18 R19 R20 R23 R24 R29 R30 R35 R36 R39 R40 R41 R42 R43 R44 R45 R46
